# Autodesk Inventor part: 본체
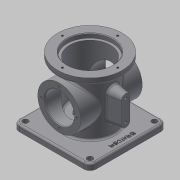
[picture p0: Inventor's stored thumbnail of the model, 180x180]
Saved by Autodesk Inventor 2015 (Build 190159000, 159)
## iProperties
Created: 2017-08
Part Number: 본체
Material: 알루미늄 6061
Document SubType Name: Modeling
Designer: mduedu
Density: 2.71 g/cm^3
Mass: 951.042 g
Surface Area: 966.503 cm^2
Volume: 350.938 cm^3
Appearance: 기본값
Author: mduedu
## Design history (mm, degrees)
sketch "스케치1"
  geometry: L1 (-62.5, -62.5)-(62.5, -62.5); L2 (62.5, -62.5)-(62.5, 62.5); L3 (62.5, 62.5)-(-62.5, 62.5); L4 (-62.5, 62.5)-(-62.5, -62.5); L5 (-62.5, -62.5)-(62.5, 62.5); L6 (62.5, -62.5)-(-62.5, 62.5); 1 further point
  constraints: 12 end point, 2 midpoint, 2 parallel, 1 horizontal, 1 perpendicular
  dimensions: "d232" = 125 distance of L3.end L2.end; "d233" = 125 distance of L2.end L1.end
extrude "돌출1" new body sketch "스케치1" distance "d5" = 10; taper "d6" = 0 deg
sketch "스케치2"
  geometry: C1 r 38 at (0, 0); 1 further point
  constraints: 1 centre point, 1 coincident
  dimensions: "d111" = 76 diameter of C1
extrude "돌출2" join sketch "스케치2" distance "d12" = 88; taper "d13" = 0 deg
sketch "스케치3"
  geometry: C1 r 52.5 at (0, 0); 1 further point
  constraints: 1 centre point, 1 coincident
  dimensions: "d114" = 105 diameter of C1
extrude "돌출3" join sketch "스케치3" distance "d19" = 10; taper "d20" = 0 deg
sketch "스케치4"
  geometry: C1 r 33 at (0, 0); 1 further point
  constraints: 1 centre point, 1 coincident
  dimensions: "d115" = 66 diameter of C1
extrude "돌출4" cut sketch "스케치4" distance "d26" = 86; taper "d27" = 0 deg
sketch "스케치5"
  geometry: C1 r 37 at (0, 0); 1 further point
  constraints: 1 centre point, 1 coincident
  dimensions: "d116" = 74 diameter of C1
extrude "돌출5" cut sketch "스케치5" distance "d29" = 7; taper "d30" = 0 deg
node "작업 평면1"
sketch "스케치18"
  geometry: L1 (-62.5, 0)-(62.5, 0) reference; C1 r 35 at (0, 54); 1 further point
  constraints: 1 centre point, 1 vertical alignment
  dimensions: "d118" = 70 diameter of C1; "d234" = 54 distance from line of C1.centre L1
extrude "돌출9" join sketch "스케치18" stored distance "d120" = 10; taper "d121" = 0 deg
hole "구멍8" diameter "d124" = 48; stored, may be unused: countersink angle "d128" = 90 deg, drill point angle "d130" = 118 deg; dims "d122" = 10, "d123" = 10, "d125" = 6, "d126" = 4, "d127" = 2, "d129" = 8
sketch "스케치9"
  geometry: C1 r 33 at (0, 0); 1 further point
  constraints: 1 centre point, 1 coincident
  dimensions: "d131" = 66 diameter of C1
extrude "돌출8" cut sketch "스케치9" distance "d43" = 16; taper "d44" = 0 deg
node "작업 평면2"
fillet "모깎기9" dims "d137" = 3
fillet "모깎기10" dims "d138" = 3
chamfer "모따기2" distance "d139" = 1; stored, may be unused: second distance "d140" = 2, angle "d141" = 45 deg
fillet "모깎기11" dims "d142" = 3
fillet "모깎기12" dims "d143" = 3
fillet "모깎기13" dims "d144" = 3
node "작업 평면3"
sketch "스케치20"
  geometry: L1 (108, -52.5)-(108, 52.5) reference; L2 (37, 7)-(71, 7); L3 (37, -7)-(71, -7); L4 (0, -33)-(0, 33) reference; A1 r 7 centre (37, 0) between (37, 7) and (37, -7); A2 r 7 centre (71, 0) between (71, 7) and (71, -7); 1 further point
  constraints: 4 end point, 4 point on circle, 3 tangent, 2 centre point, 2 horizontal alignment, 1 parallel, 1 perpendicular
  dimensions: "d203" = 14 diameter of A1; "d206" = 30 distance edge to line of A2 L1; "d207" = 48 dimension on A2 A1 (derived); "d236" = 30 distance edge to line of A1 L4
extrude "돌출10" join sketch "스케치20" stored distance "d152" = 10; taper "d153" = 10 deg
sketch "스케치21"
  geometry: C1 r 7 at (0, 71) reference; C2 r 7 at (0, 37) reference; 3 further points
  constraints: 2 coincident
hole "구멍12" sketch "스케치21" at (0, 71), (0, 37) diameter "d219" = 4.134; stored, may be unused: countersink angle "d223" = 90 deg, drill point angle "d225" = 118 deg; dims "d220" = 6, "d221" = 4, "d222" = 2, "d224" = 8
fillet "모깎기18" dims "d229" = 3
sketch "스케치23"
  geometry: C1 r 20 at (0, 0); 1 further point
  constraints: 1 centre point, 1 coincident
  dimensions: "d168" = 40 diameter of C1
extrude "돌출12" cut sketch "스케치23" stored distance "d169" = 148.25; taper "d170" = 0 deg
sketch "스케치28"
  geometry: L1 (62.5, -62.5)-(62.5, 62.5) reference; 2 further points
  constraints: 1 horizontal alignment, 1 other
  dimensions: "d238" = 10 distance from line of point (52.5, 0) L1
feature "엠보싱4" sketch "스케치28" dims "d239" = 0.5, "d240" = 0
sketch "스케치25" dims "d178" = 58
  geometry: C1 r 35 at (0, 0) reference; 3 further points
  constraints: 2 vertical alignment, 1 coincident, 2 other
hole "구멍10" sketch "스케치25" at (0, 29) diameter "d179" = 3.242; stored, may be unused: countersink angle "d183" = 90 deg, drill point angle "d185" = 118 deg; dims "d180" = 4, "d181" = 4, "d182" = 2, "d184" = 6
sketch "스케치26" dims "d189" = 90
  geometry: 3 further points
  constraints: 2 vertical alignment, 1 coincident, 2 other
hole "구멍11" sketch "스케치26" at (0, 45) diameter "d190" = 3.242; stored, may be unused: countersink angle "d194" = 90 deg, drill point angle "d196" = 118 deg; dims "d191" = 4, "d192" = 4, "d193" = 2, "d195" = 6
chamfer "모따기4" distance "d200" = 1; stored, may be unused: second distance "d201" = 2, angle "d202" = 45 deg
fillet "모깎기19" dims "d241" = 10
sketch "스케치29"
  geometry: A1 r 10 centre (-52.5, 52.5) between (-52.5, 62.5) and (-62.5, 52.5) reference; A2 r 10 centre (52.5, 52.5) between (62.5, 52.5) and (52.5, 62.5) reference; A3 r 10 centre (52.5, -52.5) between (52.5, -62.5) and (62.5, -52.5) reference; A4 r 10 centre (-52.5, -52.5) between (-62.5, -52.5) and (-52.5, -62.5) reference; 5 further points
  constraints: 4 coincident
hole "구멍13" sketch "스케치29" at (-52.5, 52.5), (52.5, 52.5), (52.5, -52.5), (-52.5, -52.5) diameter "d242" = 9; stored, may be unused: countersink angle "d246" = 90 deg, drill point angle "d248" = 118 deg; dims "d243" = 6, "d244" = 4, "d245" = 2, "d247" = 8
fillet "모깎기20" dims "d249" = 3
node "솔리드1"
mirror "대칭2"
pattern_circular "원형 패턴1" dims angle "d187" = 360 deg
mirror "대칭3"
pattern_circular "원형 패턴2" dims angle "d198" = 360 deg
other parameters: "d147" = 58
